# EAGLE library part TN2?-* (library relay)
SLIM POLARIZED RELAY NAiS Source: http://www.mew-europe.com/.. en_ds_61019_0000.pdf
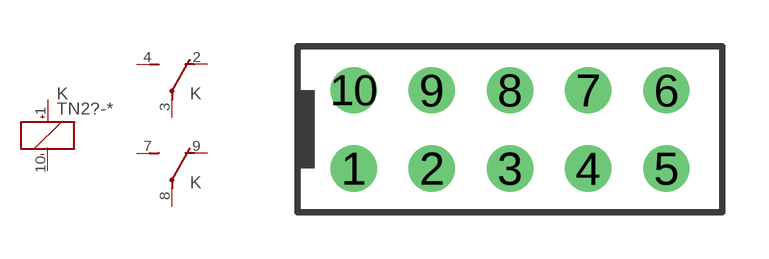
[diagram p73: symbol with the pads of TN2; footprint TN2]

Designator prefix K; gates -=K+- 1=U 2=U

## TN2-3V (MF: AROMAT/ MATSUSHITA; MPN: TN2-3V; OC_FARNELL: unknown; OC_NEWARK: 90F3177), TN2-4.5V (MF: AROMAT/ MATSUSHITA; MPN: TN2-4.5V; OC_FARNELL: 1231845; OC_NEWARK: 64K3188), TN2-5V (MF: AROMAT/ MATSUSHITA; MPN: TN2-5V; OC_FARNELL: 1200955; OC_NEWARK: 64K3189), TN2-6V (MF: AROMAT/ MATSUSHITA; MPN: TN2-6V; OC_FARNELL: unknown; OC_NEWARK: 90F3180), TN2-9V (MF: AROMAT/ MATSUSHITA; MPN: TN2-9V; OC_FARNELL: unknown; OC_NEWARK: 90F3181), TN2-12V (MF: AROMAT/ MATSUSHITA; MPN: TN2-12V; OC_FARNELL: 1200956; OC_NEWARK: 65K1079), TN2-24V (MF: AROMAT/ MATSUSHITA; MPN: TN2-24V; OC_FARNELL: 910405; OC_NEWARK: 64K3187), TN2-48V (MPN: TN2-48V; OC_FARNELL: unknown; OC_NEWARK: 13P9184)  [TN2]
1  -:+  pas
2  1:O  pas
3  1:P  pas
4  1:S  pas
7  2:S  pas
8  2:P  pas
9  2:O  pas
10  -:-  pas

## TN2-L-3V (MF: AROMAT/ MATSUSHITA; MPN: TN2-L-3V; OC_FARNELL: unknown; OC_NEWARK: 90F3184), TN2-L-4.5V (MPN: TN2-L-4.5V; OC_FARNELL: unknown; OC_NEWARK: 15P9757), TN2-L-5. (OC_FARNELL: unknown; OC_NEWARK: unknown), TN2-L-6V (MF: AROMAT/ MATSUSHITA; MPN: TN2-L-6V; OC_FARNELL: unknown; OC_NEWARK: 90F3169), TN2-L-9V (OC_FARNELL: unknown; OC_NEWARK: unknown), TN2-L-12V (MF: AROMAT/ MATSUSHITA; MPN: TN2-L-12V; OC_FARNELL: unknown; OC_NEWARK: 90F3171), TN2-L-24V (OC_FARNELL: unknown; OC_NEWARK: unknown)  [TN2]
1  -:-  pas
2  1:O  pas
3  1:P  pas
4  1:S  pas
7  2:S  pas
8  2:P  pas
9  2:O  pas
10  -:+  pas

## Footprint TN2 (pad centres in mm)
SLIM POLARIZED RELAY NAiS Source: http://www.mew-europe.com/.. en_ds_61019_0000.pdf
drill 1 round: 1 -5.08,-1.27; 2 -2.54,-1.27; 3 0,-1.27; 4 2.54,-1.27; 5 5.08,-1.27; 6 5.08,1.27; 7 2.54,1.27; 8 0,1.27; 9 -2.54,1.27; 10 -5.08,1.27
